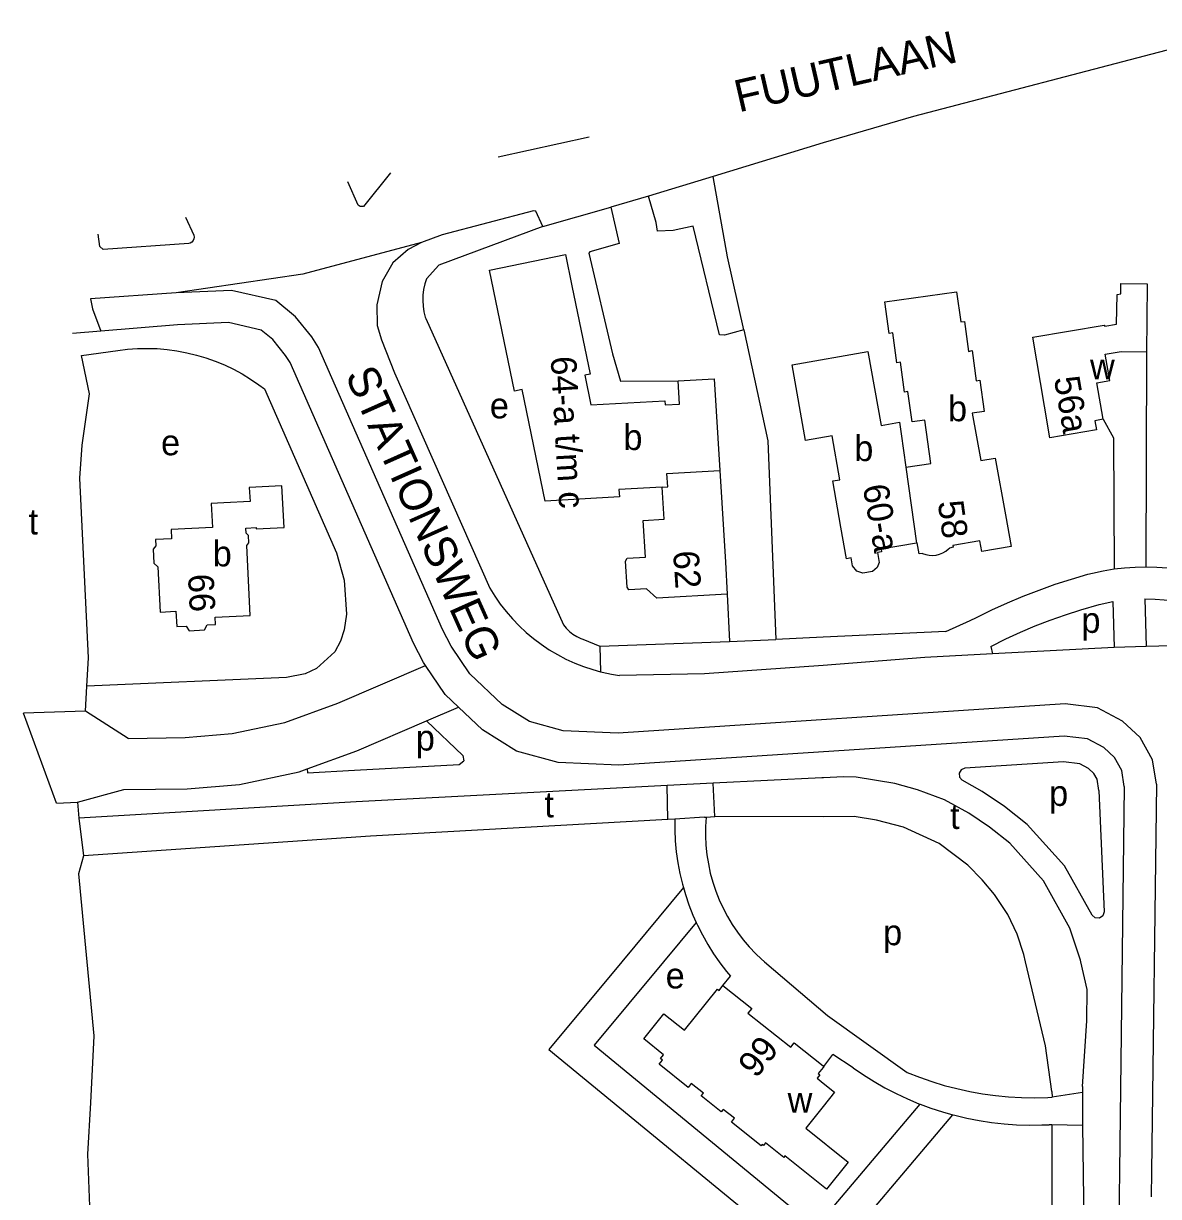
# Model space of a CAD drawing. Extents: x 161775 to 163181, y 382878 to 383925.
# Drawn here: x 161775.2 to 161952.3, y 383537.4 to 383720.4 of the extents above; entities that cross this region are included whole.
import ezdxf

# ---------------------------------------------------------------- set-up
doc = ezdxf.new("R2010")
doc.units = 0
for name, color, linetype in [('BLT_Basislijn', 7, 'Continuous'), ('BLT_Bebouwing', 7, 'Continuous'), ('BLT_Centroide', 7, 'Continuous'), ('BLT_Huisnummer', 7, 'Continuous'), ('BLT_Huisnummer_reeks', 7, 'Continuous'), ('BLT_Onderverdeling_panden', 7, 'Continuous'), ('BLT_Straatnaam', 7, 'Continuous'), ('BLT_Vlakafsluiter', 7, 'Continuous')]:
    doc.layers.add(name, color=color, linetype=linetype)

msp = doc.modelspace()

# ---------------------------------------------------------------- linework, layer by layer
at = {"layer": 'BLT_Basislijn'}
for p, q in [((161849.3, 383699.6), (161863.49, 383702.74)), ((161882.86, 383696.55), (161872.76, 383693.48)), ((161872.76, 383693.48), (161866.87, 383691.77)), ((161856.29, 383688.72), (161866.87, 383691.77)), ((161800.51, 383690.22), (161801.83, 383687.38)), ((161838, 383674.37), (161859.48, 383626.6)), ((161787.32, 383672.41), (161782.9, 383672.04)), ((161950.43, 383669.2), (161950.34, 383635.64)), ((161885.04, 383631.37), (161885.39, 383624)), ((161945.22, 383630.23), (161945.39, 383623.05)), ((161950.21, 383630.64), (161950.39, 383623.19)), ((161862.52, 383624.33), (161865.17, 383623.24)), ((161865.17, 383623.24), (161885.39, 383624)), ((161885.39, 383624), (161892.63, 383624.32)), ((161865.17, 383623.24), (161865.27, 383619.26)), ((161926.18, 383623.23), (161926.43, 383622.06)), ((161784.9, 383613.09), (161785.12, 383617.04)), ((161784.9, 383613.09), (161775.24, 383612.8)), ((161791.56, 383608.86), (161784.9, 383613.09)), ((161838.1, 383611.58), (161843.11, 383613.73)), ((161783.68, 383598.93), (161790.88, 383600.91)), ((161882.86, 383601.86), (161875.68, 383601.49)), ((161875.76, 383596.22), (161875.68, 383601.49)), ((161883.09, 383596.69), (161882.86, 383601.86)), ((161943.04, 383600.71), (161943.84, 383581.8)), ((161780.4, 383598.77), (161783.68, 383598.93)), ((161783.68, 383598.93), (161783.9, 383596.42)), ((161881.49, 383596.55), (161876.85, 383596.28)), ((161881.49, 383596.55), (161881.74, 383596.57)), ((161881.74, 383596.57), (161883.09, 383596.69)), ((161783.9, 383596.42), (161784.62, 383590.53)), ((161876.85, 383596.28), (161875.76, 383596.22)), ((161884.37, 383570.31), (161885.54, 383571.78)), ((161900.13, 383557.67), (161901.5, 383559.56)), ((161904.67, 383557.47), (161901.5, 383559.56)), ((161940.47, 383554.54), (161940.47, 383553.63)), ((161935.67, 383553.77), (161935.73, 383552.87)), ((161940.47, 383553.63), (161935.73, 383552.87)), ((161940.47, 383553.63), (161940.49, 383548.45)), ((161935.7, 383548.58), (161935.27, 383548.59)), ((161940.49, 383548.45), (161935.7, 383548.58))]:
    msp.add_line(p, q, dxfattribs=at)
for points in [[(161972.7, 383720.42), (161972.4, 383720.39), (161953.48, 383716.22), (161914.12, 383705.92), (161900, 383701.78), (161882.86, 383696.55)], [(161832.5, 383697.13), (161828.3, 383691.84), (161827.79, 383691.87), (161827.47, 383692.06), (161825.82, 383695.69)], [(161887.65, 383672.6), (161885.07, 383684.03), (161882.86, 383696.55)], [(161887.65, 383672.6), (161884.62, 383671.79), (161883.82, 383671.82), (161879.74, 383688.81), (161876.58, 383688.1), (161874.14, 383688), (161873.93, 383689.39), (161872.76, 383693.48)], [(161866.87, 383691.77), (161868.2, 383686.1), (161863.58, 383684.8), (161863.42, 383684.6), (161867.15, 383668.87), (161868.36, 383664.59), (161877.38, 383664.66)], [(161856.29, 383688.72), (161855.2, 383691.16), (161854.82, 383691.2), (161840.54, 383687.43), (161837.35, 383686.26)], [(161856.29, 383688.72), (161840.06, 383682.72), (161838.11, 383680.6)], [(161801.06, 383686.08), (161787.66, 383685.17), (161787.14, 383685.6), (161786.91, 383687.57)], [(161801.83, 383687.38), (161801.86, 383687.09), (161801.82, 383686.8), (161801.7, 383686.54), (161801.51, 383686.32), (161801.27, 383686.15), (161801.06, 383686.08)], [(161837.35, 383686.26), (161835.28, 383685.15), (161832.89, 383683.07), (161831.21, 383680.14), (161830.35, 383676.54), (161830.44, 383673.28), (161831.11, 383671.08), (161833.15, 383665.93), (161847.99, 383632.33)], [(161838.11, 383680.6), (161837.85, 383679.77), (161837.66, 383678.91), (161837.56, 383678.04), (161837.53, 383677.17), (161837.59, 383676.3), (161837.72, 383675.43), (161837.93, 383674.58), (161838, 383674.37)], [(161799.06, 383678.39), (161785.7, 383677.45), (161785.99, 383675.87), (161787.32, 383672.41)], [(161951.99, 383601.74), (161951.37, 383605.51), (161949.45, 383608.98), (161946.72, 383611.55), (161942.8, 383613.64), (161937.74, 383614.25), (161868.04, 383609.68), (161859.44, 383610.05), (161854.2, 383611.5), (161849.92, 383614.17), (161844.86, 383618.96), (161841.96, 383623.24), (161840.62, 383625.86), (161821.26, 383669.87), (161820.22, 383671.53), (161817.69, 383674.65), (161814.59, 383677.17), (161807.69, 383678.78), (161799.06, 383678.39)], [(161837.96, 383620.23), (161837.64, 383620.69), (161836.1, 383623.72), (161816.83, 383667.52), (161816.14, 383668.62), (161814.13, 383671.1), (161812.33, 383672.57), (161807.23, 383673.75), (161799.29, 383673.4), (161787.32, 383672.41)], [(161887.65, 383672.6), (161891.39, 383655.32), (161892.63, 383624.32)], [(161784.3, 383668.61), (161789.94, 383669.4), (161791.48, 383669.59), (161793.02, 383669.7), (161794.57, 383669.73), (161796.12, 383669.68), (161797.66, 383669.55), (161799.19, 383669.34), (161800.71, 383669.05), (161802.22, 383668.69), (161803.7, 383668.24), (161805.16, 383667.72), (161806.59, 383667.13), (161807.99, 383666.46), (161809.35, 383665.73), (161810.67, 383664.92), (161811.95, 383664.04), (161812.82, 383663.4)], [(161785.12, 383617.04), (161785.36, 383621.42), (161784.03, 383649.45), (161784.41, 383654.6), (161785.55, 383662.61), (161784.3, 383668.61)], [(161812.82, 383663.4), (161824.06, 383637.82), (161825.25, 383633.57), (161825.61, 383628.24), (161825.25, 383625.78), (161824.7, 383624.02), (161823.84, 383622.36), (161820.97, 383619.75), (161819.18, 383618.92), (161816.25, 383618.38), (161785.12, 383617.04)], [(161943.68, 383658.66), (161945.3, 383655.75), (161945.41, 383635.3)], [(161942.05, 383634.67), (161943.69, 383635.02), (161945.41, 383635.3)], [(161945.41, 383635.3), (161947.01, 383635.49), (161948.69, 383635.6), (161950.34, 383635.64)], [(161950.34, 383635.64), (161952.05, 383635.59), (161953.72, 383635.47), (161955.39, 383635.26), (161957.05, 383634.98)], [(161923.95, 383627.71), (161926.34, 383628.9), (161928.76, 383630.01), (161931.21, 383631.05), (161933.69, 383632.02), (161936.2, 383632.91), (161938.73, 383633.73), (161941.29, 383634.47), (161942.05, 383634.67)], [(161847.99, 383632.33), (161848.78, 383631.06), (161849.63, 383629.83), (161850.55, 383628.64), (161851.53, 383627.51), (161852.57, 383626.43), (161853.67, 383625.41), (161854.82, 383624.45), (161856.02, 383623.55), (161857.26, 383622.71), (161858.55, 383621.94), (161859.88, 383621.25), (161861.24, 383620.62), (161862.63, 383620.07), (161864.06, 383619.59), (161865.27, 383619.26)], [(161926.18, 383623.23), (161928.5, 383624.39), (161930.78, 383625.44), (161933.09, 383626.42), (161935.43, 383627.33), (161937.8, 383628.17), (161940.19, 383628.94), (161943.05, 383629.77)], [(161943.05, 383629.77), (161945.22, 383630.23)], [(161950.21, 383630.64), (161951.79, 383630.6), (161953.23, 383630.49), (161954.66, 383630.32), (161956.13, 383630.06)], [(161919.14, 383625.54), (161922.93, 383627.26), (161923.95, 383627.71)], [(161859.48, 383626.6), (161859.92, 383626.05), (161860.42, 383625.55), (161860.97, 383625.12), (161861.57, 383624.75), (161862.21, 383624.45), (161862.52, 383624.33)], [(161919.14, 383625.54), (161900, 383624.65), (161892.63, 383624.32)], [(161984.53, 383623.99), (161970.12, 383623.75), (161950.39, 383623.19)], [(161945.39, 383623.05), (161926.43, 383622.06)], [(161950.39, 383623.19), (161945.39, 383623.05)], [(161915.88, 383621.5), (161900, 383620.25), (161881.49, 383618.93), (161868.21, 383618.66)], [(161926.43, 383622.06), (161915.88, 383621.5)], [(161791.56, 383608.86), (161800.44, 383609.02), (161807.79, 383609.61), (161816.03, 383611.35), (161824.3, 383614.36), (161837.96, 383620.23)], [(161843.11, 383613.73), (161841.03, 383615.7), (161837.96, 383620.23)], [(161865.27, 383619.26), (161865.5, 383619.19), (161866.96, 383618.87), (161868.21, 383618.66)], [(161946.98, 383601.36), (161946.58, 383603.85), (161945.45, 383605.87), (161943.78, 383607.45), (161941.27, 383608.79), (161937.61, 383609.23), (161868.1, 383604.67), (161858.65, 383605.08), (161852.17, 383606.87), (161846.84, 383610.2), (161843.11, 383613.73)], [(161819.52, 383604.1), (161827.25, 383606.92), (161838.1, 383611.58)], [(161838.1, 383611.58), (161843.77, 383606.22), (161843.92, 383605.34)], [(161790.88, 383600.91), (161800.79, 383601.02), (161808.93, 383601.67), (161818.24, 383603.64), (161819.52, 383604.1)], [(161819.52, 383604.1), (161819.54, 383603.5), (161826.86, 383603.93), (161843.21, 383604.79), (161843.92, 383605.34)], [(161922.11, 383604.2), (161921.52, 383603.97), (161921.2, 383603.42), (161921.26, 383602.8), (161921.69, 383602.33)], [(161943.04, 383600.71), (161942.74, 383602.51), (161942.26, 383603.38), (161941.42, 383604.17), (161940.04, 383604.9), (161937.5, 383605.21), (161922.11, 383604.2)], [(161940.22, 383574.02), (161940.17, 383574.25), (161938.51, 383579.27), (161934.37, 383586.65), (161929.12, 383592.51), (161925.95, 383595), (161922.72, 383597.18), (161918.93, 383599.29), (161914.72, 383600.85), (161911.2, 383601.83), (161905.15, 383602.79), (161903.17, 383602.87), (161900.05, 383602.72), (161899.8, 383602.71), (161882.86, 383601.86)], [(161941.96, 383581.27), (161937.64, 383588.99), (161931.86, 383595.43), (161928.31, 383598.23), (161924.82, 383600.6), (161921.69, 383602.33)], [(161875.68, 383601.49), (161827.13, 383598.94), (161783.9, 383596.42)], [(161946.98, 383601.36), (161946.24, 383541.32), (161946.19, 383537.4), (161945.92, 383518.77), (161947.18, 383498.26), (161948.93, 383485.15), (161950.84, 383474.34), (161954.81, 383457.81), (161955.82, 383453.93), (161971.26, 383394.12), (161973.42, 383383.64), (161973.93, 383380.26), (161974.3, 383375.36), (161974.29, 383372.57), (161974.18, 383368.85), (161973.25, 383360.73), (161969.88, 383348.44), (161965.65, 383337.35), (161956.35, 383324.34)], [(161951.99, 383601.74), (161951.24, 383541.26), (161951.19, 383537.33)], [(161881.74, 383596.57), (161881.65, 383595.1), (161881.64, 383593.64), (161881.71, 383592.18), (161881.86, 383590.72), (161882.09, 383589.28), (161882.39, 383587.85), (161882.78, 383586.44), (161883.24, 383585.05), (161883.78, 383583.69), (161884.39, 383582.36), (161885.07, 383581.07), (161885.82, 383579.82), (161886.64, 383578.61), (161887.53, 383577.44), (161888.47, 383576.33), (161889.48, 383575.27), (161890.33, 383574.46)], [(161931.58, 383574.02), (161931.31, 383575.15), (161930.25, 383578.32), (161928.8, 383581.4), (161926.72, 383584.49), (161924.82, 383586.81), (161922.59, 383589.1), (161918.13, 383592.44), (161912.53, 383594.99), (161908.35, 383596.12), (161904.83, 383596.66), (161900, 383596.64), (161883.09, 383596.69)], [(161875.76, 383596.22), (161829.4, 383593.61), (161784.62, 383590.53)], [(161876.85, 383596.28), (161876.85, 383594.58), (161876.93, 383592.87), (161877.09, 383591.17), (161877.33, 383589.47), (161877.65, 383587.79), (161878.04, 383586.13), (161878.2, 383585.58)], [(161784.62, 383590.53), (161783.84, 383587.71), (161786.2, 383562.47), (161785.71, 383552.01), (161785.24, 383543.99), (161786.03, 383523.7)], [(161878.2, 383585.58), (161868.61, 383574.02)], [(161878.2, 383585.58), (161878.52, 383584.49), (161879.07, 383582.87), (161879.69, 383581.28), (161880.2, 383580.15)], [(161943.84, 383581.8), (161943.65, 383581.18), (161943.11, 383580.8), (161942.46, 383580.84), (161941.96, 383581.27)], [(161880.2, 383580.15), (161875.11, 383574.02)], [(161880.2, 383580.15), (161880.39, 383579.72), (161881.16, 383578.2), (161882.01, 383576.71), (161882.92, 383575.26), (161883.78, 383574.02)], [(161868.61, 383574.02), (161857.23, 383560.31), (161899.5, 383525.56), (161920.24, 383550.13)], [(161875.11, 383574.02), (161864.29, 383560.98), (161898.86, 383532.56), (161915.12, 383551.8)], [(161883.78, 383574.02), (161883.9, 383573.86), (161884.94, 383572.5), (161885.54, 383571.78)], [(161890.33, 383574.46), (161890.84, 383574.02)], [(161890.84, 383574.02), (161900.69, 383565.65), (161913.12, 383556.71)], [(161935.67, 383553.77), (161934.71, 383560.91), (161931.58, 383574.02)], [(161940.47, 383554.54), (161941.14, 383564.8), (161941.19, 383569.68), (161940.22, 383574.02)], [(161904.67, 383557.47), (161906.28, 383556.37), (161907.94, 383555.33), (161909.64, 383554.35), (161911.38, 383553.45), (161913.15, 383552.62), (161914.95, 383551.86), (161915.12, 383551.8)], [(161913.12, 383556.71), (161915.02, 383555.98), (161916.95, 383555.31), (161918.9, 383554.72), (161920.88, 383554.21), (161922.87, 383553.78), (161924.88, 383553.42), (161926.9, 383553.15), (161928.93, 383552.95), (161930.97, 383552.83), (161933.01, 383552.8), (161935.05, 383552.84), (161935.73, 383552.87)], [(161915.12, 383551.8), (161916.79, 383551.18), (161918.65, 383550.58), (161920.24, 383550.13)], [(161920.24, 383550.13), (161920.53, 383550.05), (161922.44, 383549.59), (161924.36, 383549.22), (161926.29, 383548.92), (161928.24, 383548.71), (161930.19, 383548.57), (161932.15, 383548.51), (161934.1, 383548.54), (161935.27, 383548.59)], [(161935.7, 383548.58), (161935.72, 383514.8), (161935.53, 383507.55)], [(161940.49, 383548.45), (161940.96, 383514.3), (161943.59, 383490.54), (161945.3, 383477.35), (161949.98, 383457.04), (161950.03, 383456.53), (161948.04, 383455.83)]]:
    msp.add_lwpolyline(points, dxfattribs=at)
at = {"layer": 'BLT_Bebouwing'}
for p, q in [((161912.16, 383656.41), (161912.89, 383651.21)), ((161900.13, 383557.67), (161900.13, 383557.66))]:
    msp.add_line(p, q, dxfattribs=at)
for points in [[(161874.91, 383648.07), (161868.15, 383647.68), (161868.21, 383646.56), (161856.63, 383645.89), (161853.04, 383663.32), (161851.84, 383663.07), (161847.95, 383681.95), (161859.78, 383684.39), (161860.79, 383679.49), (161863.63, 383665.72), (161862.8, 383665.54), (161863.76, 383660.9), (161875.29, 383661.56), (161875.33, 383660.9), (161877.59, 383661.03), (161877.38, 383664.66)], [(161943.68, 383658.66), (161942.4, 383658.44), (161942.65, 383657), (161935.39, 383655.77), (161934.55, 383660.7), (161932.72, 383671.46), (161943.83, 383673.35), (161943.95, 383673.2), (161945.75, 383673.51), (161945.9, 383678.15), (161946.44, 383678.24), (161946.45, 383679.84), (161950.56, 383679.8), (161950.49, 383674.2), (161950.43, 383669.2)], [(161912.89, 383651.21), (161916.81, 383651.76), (161915.86, 383658.53), (161913.9, 383658.26), (161913.24, 383662.98), (161912.7, 383662.91), (161912.05, 383667.56), (161911.5, 383667.48), (161910.85, 383672.14), (161910.3, 383672.06), (161909.61, 383676.99), (161920.83, 383678.57), (161921.47, 383673.88), (161922.04, 383673.94), (161922.68, 383669.26), (161923.23, 383669.37), (161923.9, 383664.68), (161924.44, 383664.77), (161925.12, 383659.86), (161923.27, 383659.6), (161924.63, 383652.21), (161926.83, 383652.58), (161928.45, 383643.74), (161929.35, 383638.82), (161924.74, 383638.01), (161924.44, 383639.7), (161920.24, 383638.96), (161920.29, 383638.68), (161919.72, 383638.57)], [(161901.5, 383649.07), (161902.62, 383649.21), (161901.42, 383656.06), (161897.26, 383655.33), (161895.18, 383667.15), (161907, 383669.23), (161909.03, 383657.71), (161911.91, 383658.21), (161912.16, 383656.41)], [(161943.68, 383658.66), (161942.71, 383664.36), (161944.73, 383664.71), (161944.03, 383668.83), (161946.5, 383669.25), (161950.43, 383669.2)], [(161877.38, 383664.66), (161883.02, 383664.98), (161883.89, 383650.68)], [(161883.89, 383650.68), (161884.76, 383636.36), (161885.04, 383631.37)], [(161885.04, 383631.37), (161874.08, 383630.74), (161872.43, 383632.22), (161869.67, 383632.06), (161869.4, 383632.47), (161869.17, 383636.51), (161869.41, 383636.98), (161872.27, 383637.14), (161871.94, 383642.88), (161875.2, 383643.07), (161874.91, 383648.07)], [(161914.55, 383639.35), (161909.05, 383638.39), (161909.12, 383637.99), (161908.46, 383637.87), (161908.73, 383636.31), (161908.45, 383635.55), (161907.7, 383634.91), (161906.18, 383634.65), (161905.26, 383634.98), (161904.59, 383635.78), (161904.37, 383637.03), (161903.64, 383636.9), (161902.77, 383641.83), (161901.5, 383649.07)], [(161915.49, 383637.73), (161914.97, 383637.64), (161914.66, 383639.37), (161914.55, 383639.35)], [(161915.49, 383637.73), (161916.01, 383637.55), (161916.54, 383637.44), (161917.09, 383637.42), (161917.64, 383637.47), (161918.17, 383637.6), (161918.68, 383637.81), (161919.15, 383638.09), (161919.58, 383638.43), (161919.72, 383638.57)], [(161900.13, 383557.66), (161900, 383557.5), (161899.25, 383556.56), (161899.49, 383556.37), (161899.06, 383555.83), (161900, 383555.08), (161901.79, 383553.65), (161900, 383551.42), (161897.28, 383548.02), (161903.9, 383542.73), (161900.53, 383538.52), (161894.05, 383543.71), (161893.85, 383543.46), (161891.02, 383545.73), (161890.69, 383545.33), (161890.49, 383545.48), (161890.33, 383545.28), (161885.68, 383548.99), (161886.15, 383549.59), (161884.41, 383550.98), (161884.09, 383550.59), (161880.98, 383553.08), (161881.31, 383553.49), (161879.41, 383555), (161878.93, 383554.39), (161874.4, 383558.01), (161874.93, 383558.68), (161874.64, 383558.92), (161875.11, 383559.51), (161872.05, 383561.99), (161875.17, 383565.9), (161878.37, 383563.34), (161883.51, 383569.76), (161883.77, 383569.55), (161884.37, 383570.31)], [(161884.37, 383570.31), (161888.86, 383566.73), (161888.27, 383566), (161894.94, 383560.67), (161895.5, 383561.37), (161900, 383557.77), (161900.13, 383557.67)]]:
    msp.add_lwpolyline(points, dxfattribs=at)
msp.add_lwpolyline([(161815.57, 383648.27), (161810.47, 383648.01), (161810.58, 383645.85), (161806.49, 383645.64), (161804.52, 383645.54), (161804.71, 383641.79), (161798.27, 383641.46), (161798.34, 383640.01), (161795.86, 383639.88), (161795.9, 383638.9), (161795.45, 383638.39), (161795.56, 383636.2), (161796.18, 383635.64), (161796.54, 383628.58), (161799.02, 383628.7), (161799.14, 383626.32), (161800.62, 383626.4), (161801.09, 383625.66), (161803.49, 383625.78), (161803.9, 383626.58), (161805.18, 383626.65), (161805.12, 383627.77), (161810.61, 383628.05), (161810.06, 383638.98), (161810.41, 383639.38), (161810.36, 383640.54), (161809.96, 383640.89), (161809.92, 383641.69), (161811.55, 383641.77), (161811.56, 383641.55), (161815.9, 383641.77)], close=True, dxfattribs=at)
at = {"layer": 'BLT_Onderverdeling_panden'}
msp.add_line((161912.89, 383651.21), (161914.55, 383639.35), dxfattribs=at)
msp.add_lwpolyline([(161874.91, 383648.07), (161875.76, 383648.12), (161875.64, 383650.22), (161883.89, 383650.68)], dxfattribs=at)
at = {"layer": 'BLT_Vlakafsluiter'}
msp.add_line((161780.4, 383598.77), (161775.24, 383612.8), dxfattribs=at)
for points in [[(161837.35, 383686.26), (161818.84, 383681.31)], [(161818.84, 383681.31), (161799.06, 383678.39)]]:
    msp.add_lwpolyline(points, dxfattribs=at)

# ---------------------------------------------------------------- texts
at = {"layer": 'BLT_Centroide'}
for s, p in [('w', (161941.64, 383664.91)), ('b', (161919.48, 383658.36)), ('e', (161848, 383658.8)), ('b', (161868.84, 383653.87)), ('e', (161796.7, 383653.04)), ('b', (161904.86, 383652.14)), ('t', (161776.03, 383640.69)), ('b', (161804.76, 383635.71)), ('p', (161940.3, 383625.33)), ('p', (161836.45, 383606.97)), ('t', (161856.51, 383596.54)), ('p', (161935.26, 383598.33)), ('t', (161919.81, 383594.73)), ('p', (161909.36, 383576.59)), ('e', (161875.43, 383569.85)), ('w', (161894.46, 383550.46))]:
    msp.add_text(s, height=4, dxfattribs=at).set_placement(p)
at = {"layer": 'BLT_Huisnummer'}
for s, rotation, p in [('56a', 279.6582, (161935.99, 383665.07)), ('58', 277.971, (161917.87, 383645.74)), ('62', 273.971, (161876.58, 383638.05)), ('66', 272.9204, (161800.9, 383634.45)), ('99', 51.3509, (161889.56, 383555.68))]:
    msp.add_text(s, height=4, rotation=rotation, dxfattribs=at).set_placement(p)
at = {"layer": 'BLT_Huisnummer_reeks'}
for s, rotation, p in [('64-a t/m c', 273.2816, (161857.48, 383668.4)), ('60-a', 279.9913, (161906.16, 383648.2))]:
    msp.add_text(s, height=4, rotation=rotation, dxfattribs=at).set_placement(p)
at = {"layer": 'BLT_Straatnaam'}
for s, rotation, p in [('FUUTLAAN', 12.9581, (161886.83, 383706.54)), ('STATIONSWEG', 294.0466, (161825.37, 383665.56))]:
    msp.add_text(s, height=5, rotation=rotation, dxfattribs=at).set_placement(p)

doc.saveas('drawing.dxf')
